// Mitsubishi GX Works2 project: 25.区域比较指令（ZCP）   PLC: FX3U/FX3UC

PROGRAM MAIN
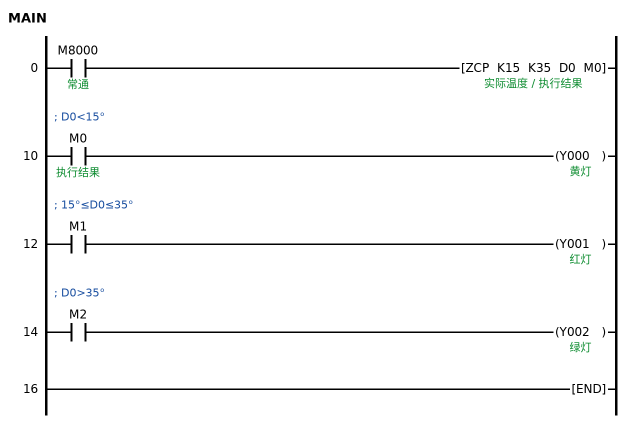
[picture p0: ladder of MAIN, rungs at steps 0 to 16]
0     LD      M8000  ; 常通
      ZCP     K15 K35 D0 M0  ; 实际温度 / 执行结果
; D0<15°
10    LD      M0  ; 执行结果
      OUT     Y000  ; 黄灯
; 15°≤D0≤35°
12    LD      M1
      OUT     Y001  ; 红灯
; D0>35°
14    LD      M2
      OUT     Y002  ; 绿灯
16    END
END_PROGRAM
